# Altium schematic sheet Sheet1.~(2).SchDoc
size A4
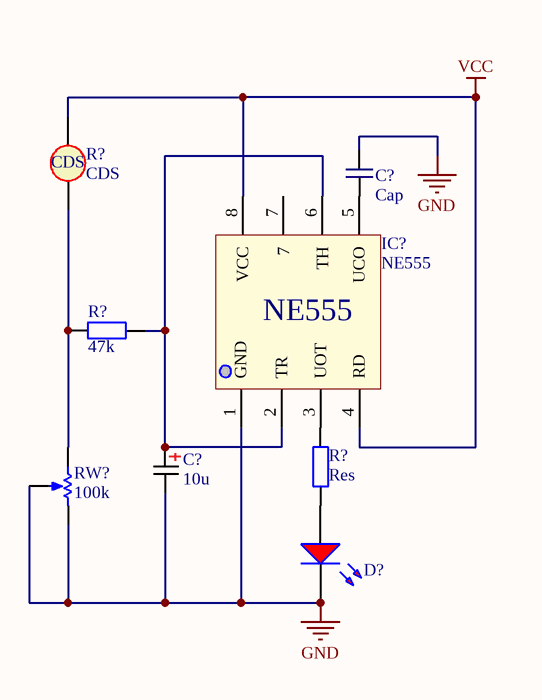
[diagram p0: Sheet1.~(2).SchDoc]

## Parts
(Parts that share a designator on the sheet are numbered #1, #2 ... from top to bottom, then left to right.)
C?#1  Cap  [RAD0.1]
C?#2  10u  [CF0.1]
D?  LED0  [LED]  (value not drawn)
IC?  NE555  [DIP-8]
R?#1  CDS  [CDS]
R?#2  47k  [AXIAL-0.3]
R?#3  Res  [AXIAL-0.3]
RW?  100k  [RW1]

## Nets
GND: C?#1.2 C?#2.2 D?.2(K) IC?.1(GND) RW?.2(TAP) RW?.3(BOT)
VCC: IC?.4(RD) IC?.8(VCC) R?#1.1
NetC?#1_1: C?#1.1 IC?.5(UCO)
NetC?#2_1: C?#2.1 IC?.2(TR) IC?.6(TH) R?#2.2
NetD?_1: D?.1(A) R?#3.1
NetIC?_3: IC?.3(UOT) R?#3.2
NetR?#1_2: R?#1.2 R?#2.1 RW?.1(TOP)

Not connected (* = marked no-connect by the designer): IC? 7

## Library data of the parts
C?#2 = Cap Pol
R?#2 R?#3 = Res: Resistor; Value: 1K
RW? = RW1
